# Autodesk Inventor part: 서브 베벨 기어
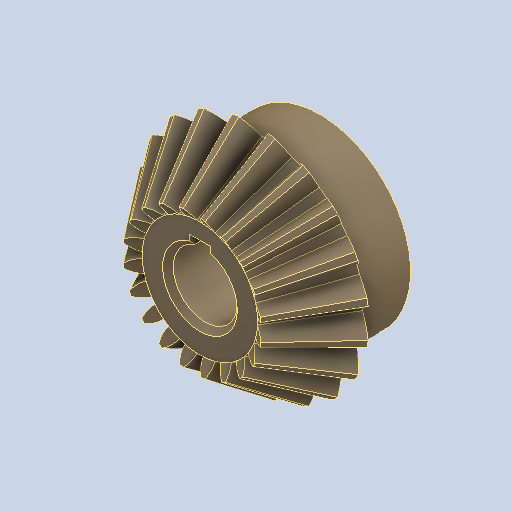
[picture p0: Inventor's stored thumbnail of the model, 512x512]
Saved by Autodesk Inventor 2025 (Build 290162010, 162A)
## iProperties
Created: 2024-07
Part Number: 서브 베벨 기어
Material: 강철, 탄소
Document SubType Name: Modeling
Designer: 계정
Density: 7.87 g/cm^3
Appearance: 기본값
Author: jhkim
Revision Number: 1
Sending System: Autodesk Inventor 2025
Preprocessor: ST-DEVELOPER v20
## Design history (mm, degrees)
node "복구된 형상1"
  node "스케치11"
feature "Solid1"
node "스케치10"
node "솔리드1"
